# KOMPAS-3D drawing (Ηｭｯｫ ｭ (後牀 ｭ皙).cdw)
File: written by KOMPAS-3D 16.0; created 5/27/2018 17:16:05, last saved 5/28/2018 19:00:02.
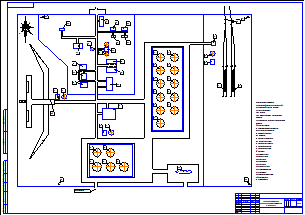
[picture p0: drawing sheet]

Sheet 1: A1, landscape

Title block, sheet 1: name: Генеральный план / перевалочной нефтебазы / г. Мурманск; scale: 1:1000; sheets: 1; sheet format: A1; stored path: C:\Users\Roman Ushak\Desktop\КР Вариант 21\Мурманск.cdw

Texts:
  2 - резервуары РВСП-3000 для ТС-1;
  6-7 - железно дорожные   сливо-наливные
  эстакады;
  8 - помещение для персонала сливо-наливной
  10 - трансформаторная подстанция;
  11 - механическая мастерская;
  14 - площадка для топлива;
  16 - водонасосная станция;
  17 - резервуары для воды;
  28 - железнодорожные пути;
  Генеральный план нефтебазы:
  1 - резервуары РВСП-3000 для бензина А95
  Запасной выезд
  K5LT_THIN_RGB_0_0_0_THICK_0.18
  K5LT_DASHED_RGB_0_0_0_SC_1_THICK_0.18
  K5LT_BASIC_RGB_0_0_255_THICK_0.6
  POLYLINE_STYLE_0.18_RGB_0_0_0
  POLYLINE_STYLE_0.60_RGB_0_0_255
  K5LT_AXLED_RGB_255_128_0_SC_1_THICK_0.18
Dimensions and other numbers on the sheet: 3 - склад пенопорошка;; 4-5 - водоемы;; 9 - насосная станция;; 12 - бытовое помещение;; 13 - котельная;; 15 - площадка для золлы;; 18 - водонапорная башня;; 19 - контора;; 20 - пожарное депо;; 21 - здание охраны;; 22 - узел связи;; 23 - лаборатория;; 24 - склад проб;; 25 - вольер для собак;; 26 - сторожевой пост;; 27 - ограждение;; 29 - речной причал.; 30 - автоэстакада.; 2; 3; 4; 8; 9; 10; 19; 25; 24; 23; 22; 21; 26; 28; 29; 13; 14; 15; 11; 12; 20; 18; 17; 16; 5; 1; 30; 6; 7; 1:1000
